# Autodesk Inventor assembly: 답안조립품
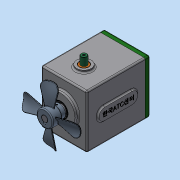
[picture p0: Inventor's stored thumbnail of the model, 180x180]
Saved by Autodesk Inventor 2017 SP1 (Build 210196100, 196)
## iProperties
Part Number: 답안조립품
Material: 일반
Document SubType Name: Assembly
Designer: MRC
Author: MRC
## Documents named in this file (17)
- C:\Users\MRC\Desktop\610205V1002\답안조립품.iam
- C:\Users\MRC\Desktop\610205V1002\본체.ipt
- C:\Users\MRC\Desktop\610205V1002\멈춤나사 M3x8.ipt
- C:\Users\MRC\Desktop\610205V1002\메인 기어 축.ipt
- C:\Users\MRC\Desktop\610205V1002\베어링 608.ipt
- C:\Users\MRC\Desktop\610205V1002\베어링 6903.ipt
- C:\Users\MRC\Desktop\610205V1002\볼트 M4 x 10.ipt
- C:\Users\MRC\Desktop\610205V1002\부시.ipt
- C:\Users\MRC\Desktop\610205V1002\서브 기어 축.ipt
- C:\Users\MRC\Desktop\610205V1002\슬라이더.ipt
- C:\Users\MRC\Desktop\610205V1002\오일 실 8 22 7.ipt
- C:\Users\MRC\Desktop\610205V1002\오일 실 17 30 8.ipt
- C:\Users\MRC\Desktop\610205V1002\커버.ipt
- C:\Users\MRC\Desktop\610205V1002\키 5 x 5 x 24.ipt
- C:\Users\MRC\Desktop\610205V1002\팬날개.ipt
- 팬날개.ipt
- C:\Users\MRC\Desktop\610205V1002\가변스프링.ipt
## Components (1 placed, 1 different names)
1. 가변스프링:1
